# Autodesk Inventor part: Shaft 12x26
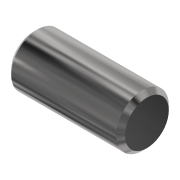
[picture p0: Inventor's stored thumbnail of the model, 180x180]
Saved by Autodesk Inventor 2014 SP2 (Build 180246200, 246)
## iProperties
Created: 2016-02
Part Number: Shaft 12x26
Material: Steel
Document SubType Name: Modeling
Designer: User
Density: 7.85 g/cm^3
Appearance: Steel - Polished
Author: User
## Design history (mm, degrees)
sketch "Sketch1"
  geometry: L1 (-13, 6)-(13, 6); L2 (13, 6)-(13, 0); L3 (13, 0)-(-13, 0); L4 (-13, 0)-(-13, 6); 2 further points
  constraints: 8 end point, 2 parallel, 1 coincident, 1 horizontal, 1 midpoint, 1 perpendicular
  dimensions: "d0" = 12 diameter of L1 L3; "d1" = 26 distance between parallel lines of L2 L4
revolve "Revolution1" sketch "Sketch1" stored, may be unused: angle "d2" = 90 deg
chamfer "Chamfer1" distance "d3" = 1; stored, may be unused: second distance "d4" = 2, angle "d5" = 45 deg
body "Solid1"
